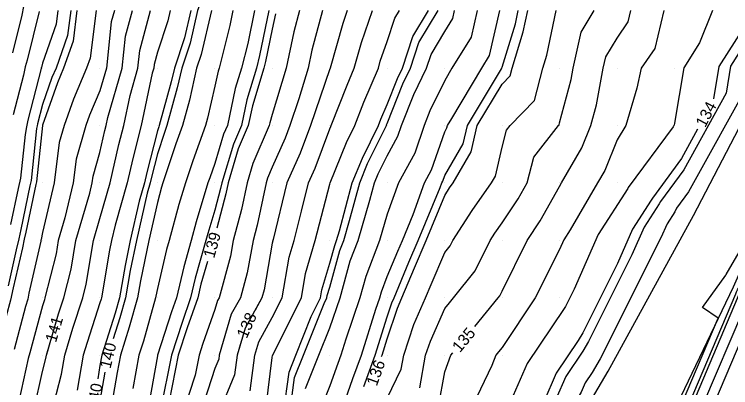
# Model space of a CAD drawing. Extents: x 2354170 to 2357230, y 866100 to 868290.
# Drawn here: x 2355375.1 to 2355499.8, y 866884.4 to 866949.4 of the extents above; entities that cross this region are included whole.
import ezdxf

# ---------------------------------------------------------------- set-up
doc = ezdxf.new("R2010")
doc.units = 0
for name, color, linetype in [('Default', 7, 'Continuous'), ('DTM Contours Major', 7, 'Continuous'), ('DTM Contours Major Text', 7, 'Continuous'), ('DTM Contours Minor', 7, 'Continuous'), ('DTM Contours Minor Text', 7, 'Continuous'), ('Exist DTM QL2 LIDAR Elevation Point', 7, 'Continuous'), ('PH Exist DTM Breakline', 7, 'Continuous')]:
    doc.layers.add(name, color=color, linetype=linetype)

msp = doc.modelspace()

# ---------------------------------------------------------------- linework, layer by layer
at = {"layer": 'Default'}
for points in [[(2355539.7, 867022.97), (2355537.35, 867020.38), (2355536.13, 867013.98), (2355531.41, 867003.55), (2355526.83, 866996.95), (2355526.72, 866996.73), (2355525.78, 866991.54), (2355519.66, 866978.94), (2355514.25, 866974.05), (2355510.02, 866968.44), (2355508.26, 866963), (2355506.26, 866955.52), (2355502.1, 866947.16), (2355497.72, 866940.29), (2355496.77, 866934.66)], [(2355490.12, 866875.79), (2355491.48, 866878.23), (2355491.88, 866879.06), (2355492.3, 866879.89), (2355492.7, 866880.74), (2355493.15, 866881.59), (2355500.95, 866899.94), (2355501.19, 866900.53), (2355501.44, 866901.06), (2355501.7, 866901.6), (2355501.96, 866902.13), (2355511.01, 866921.79), (2355511.33, 866922.42), (2355511.64, 866923.07), (2355511.95, 866923.71), (2355512.25, 866924.35), (2355512.56, 866924.99), (2355522.34, 866944.6), (2355522.74, 866945.44), (2355523.14, 866946.28), (2355523.54, 866947.12), (2355531.35, 866962.66)], [(2355374.81, 866942.66), (2355376.43, 866949.19), (2355376.71, 866950.72)], [(2355385.98, 866950.01), (2355385.32, 866944.67), (2355383.66, 866940.01), (2355382.56, 866937.42), (2355379.98, 866930.07), (2355379.96, 866930.02), (2355379.96, 866930.01), (2355379.96, 866930), (2355378.91, 866920.23), (2355378.8, 866919.75), (2355377.07, 866911.45), (2355376.81, 866910.21), (2355376.47, 866908.73), (2355374.89, 866901.78), (2355374.43, 866899.58), (2355373.67, 866896.84), (2355372.26, 866891.59), (2355371.91, 866890.32)], [(2355382.66, 866950.01), (2355382.36, 866947.62), (2355379.98, 866940.88), (2355379.78, 866940.11), (2355379.76, 866940.02), (2355379.74, 866939.92), (2355377.41, 866930.93), (2355377.19, 866929.78), (2355376.94, 866928.44), (2355376.12, 866920.82), (2355375.74, 866919.06), (2355374.42, 866912.77)], [(2355374.59, 866852.56), (2355376.35, 866859.24), (2355376.76, 866860.65), (2355379.04, 866869.55), (2355379.14, 866869.95), (2355379.23, 866870.27), (2355379.98, 866873.65), (2355381.33, 866878.66), (2355381.57, 866880.01), (2355383.28, 866886.7), (2355383.86, 866890.01), (2355385.26, 866894.73), (2355386.97, 866900.01), (2355387.58, 866902.41), (2355388.84, 866910.01), (2355389.98, 866913.85), (2355391.75, 866920.01), (2355393.27, 866926.71), (2355394.11, 866930.01), (2355395.21, 866935.24), (2355396.59, 866940.01), (2355396.91, 866943.08), (2355398.78, 866950.01)], [(2355379.41, 866949.88), (2355377.3, 866941.39), (2355376.95, 866940.21), (2355376.65, 866938.76), (2355374.86, 866931.85)], [(2355392.49, 866950.01), (2355391.95, 866948.03), (2355391.13, 866940.01), (2355389.98, 866936.05), (2355388.17, 866931.81), (2355387.54, 866930.01), (2355385.84, 866924.14), (2355385.33, 866920.01), (2355383.89, 866913.92), (2355382.73, 866910.01), (2355382.34, 866907.65), (2355380.4, 866900.01), (2355380.3, 866899.69), (2355379.98, 866898.61), (2355377.79, 866890.46), (2355377.51, 866889.47), (2355375.87, 866882), (2355375.45, 866880.29), (2355374.91, 866878.2)], [(2355389.31, 866950.01), (2355388.27, 866941.72), (2355387.66, 866940.01), (2355385.37, 866934.62), (2355383.75, 866930.01), (2355382.9, 866927.08), (2355382.02, 866920.01), (2355379.98, 866911.38), (2355379.72, 866910.14), (2355379.69, 866910.03), (2355379.66, 866909.9), (2355377.61, 866900.84), (2355377.4, 866899.81), (2355377.04, 866898.53), (2355375.02, 866891.02)], [(2355382.76, 866897.15), (2355382.78, 866897.21), (2355383.69, 866900.01), (2355384.96, 866905.03), (2355385.79, 866910.01), (2355388.22, 866918.26), (2355388.64, 866920.01), (2355388.79, 866921.2), (2355389.98, 866925.32), (2355390.84, 866929.14), (2355391.06, 866930.01), (2355391.35, 866931.39), (2355393.86, 866940.01), (2355394.43, 866945.55), (2355395.63, 866950.01)], [(2355402.2, 866950.01), (2355401.78, 866948.21), (2355399.98, 866942.78), (2355399.39, 866940.6), (2355399.33, 866940.01), (2355399.06, 866939.1), (2355397.16, 866930.01), (2355395.7, 866924.28), (2355394.73, 866920.01), (2355392.61, 866912.64), (2355392.01, 866910.01), (2355391.66, 866908.33), (2355390.24, 866900.01), (2355390.19, 866899.8), (2355389.98, 866899.14), (2355387.74, 866892.25), (2355387.07, 866890.01), (2355386.02, 866883.96)], [(2355405.79, 866950.01), (2355404.69, 866945.29), (2355402.94, 866940.01), (2355402.39, 866937.6), (2355400.29, 866930.01), (2355400.21, 866929.78), (2355399.98, 866929.08), (2355398.13, 866921.85), (2355397.72, 866920.01), (2355396.8, 866916.83), (2355395.24, 866910.01), (2355394.34, 866905.65), (2355393.38, 866900.01), (2355392.64, 866897.35), (2355390.29, 866890.01), (2355390.24, 866889.74), (2355389.98, 866888.22), (2355389.58, 866885.91)], [(2355409.37, 866950.01), (2355407.6, 866942.38), (2355406.81, 866940.01), (2355405.55, 866934.43), (2355404.33, 866930.01), (2355403.16, 866926.82), (2355400.93, 866920.01), (2355400.71, 866919.28), (2355399.98, 866916.59), (2355398.47, 866910.01), (2355397.02, 866902.97), (2355396.51, 866900.01), (2355395.09, 866894.9), (2355393.53, 866890.01), (2355392.98, 866887), (2355391.76, 866880.01)], [(2355413.11, 866950.01), (2355412.57, 866947.41), (2355410.7, 866940.01), (2355410.53, 866939.45), (2355409.98, 866936.84), (2355408.71, 866931.27), (2355408.36, 866930.01), (2355406.12, 866923.87), (2355404.85, 866920.01), (2355403.73, 866916.26), (2355402.03, 866910.01), (2355401.57, 866908.41), (2355399.98, 866901.65), (2355399.69, 866900.29), (2355399.65, 866900.01), (2355397.54, 866892.45), (2355396.76, 866890.01), (2355395.72, 866884.26)], [(2355416.88, 866950.01), (2355415.69, 866944.29), (2355414.61, 866940.01), (2355413.53, 866936.45), (2355412.16, 866930.01), (2355411.51, 866928.48), (2355409.98, 866923.37), (2355409.08, 866920.91), (2355408.78, 866920.01), (2355406.75, 866913.24), (2355405.87, 866910.01), (2355404.57, 866905.42), (2355403.29, 866900.01), (2355402.43, 866897.56), (2355400, 866890.01), (2355399.98, 866889.9), (2355398.46, 866881.52)], [(2355424.72, 866950.01), (2355423.7, 866946.29), (2355422.38, 866940.01), (2355419.98, 866931.92), (2355419.53, 866930.45), (2355419.44, 866930.01), (2355416.61, 866923.37), (2355415.6, 866920.01), (2355414.6, 866915.39), (2355413.18, 866910.01), (2355412.7, 866907.28), (2355410.7, 866900.01), (2355410.44, 866899.55), (2355409.98, 866897.97), (2355407.91, 866892.08), (2355407.24, 866890.01), (2355406.55, 866886.58), (2355404.41, 866880.01)], [(2355433.03, 866950.01), (2355432.24, 866947.74), (2355430.04, 866940.01), (2355430.02, 866939.96), (2355429.98, 866939.85), (2355426.62, 866930.01), (2355424.8, 866925.18), (2355422.53, 866920.01), (2355420.1, 866910.14), (2355420.07, 866910.01), (2355420.05, 866909.94), (2355419.98, 866909.51), (2355418.55, 866901.43), (2355418.16, 866900.01), (2355415.23, 866894.76), (2355413.84, 866890.01), (2355413.39, 866886.59), (2355410.67, 866880.01), (2355410.5, 866879.49), (2355409.98, 866877.99), (2355408.27, 866871.72), (2355407.71, 866870.01), (2355406.7, 866866.73), (2355405.8, 866863.82)], [(2355428.74, 866950.01), (2355426.86, 866943.12), (2355426.21, 866940.01), (2355424.62, 866934.65), (2355423.03, 866930.01), (2355422.2, 866927.79), (2355419.98, 866922.74), (2355419.16, 866920.82), (2355418.92, 866920.01), (2355417.32, 866912.66), (2355416.62, 866910.01), (2355415.63, 866904.36), (2355414.43, 866900.01), (2355412.83, 866897.15), (2355410.74, 866890.01), (2355410.65, 866889.33), (2355409.98, 866887.7), (2355407.47, 866880.01)], [(2355420.54, 866949.45), (2355419.98, 866946.78), (2355418.82, 866941.17), (2355418.52, 866940.01), (2355416.53, 866933.45), (2355415.8, 866930.01), (2355414.06, 866925.93), (2355412.28, 866920.01), (2355411.87, 866918.11), (2355410.3, 866912.12)], [(2355416.14, 866883.85), (2355416.93, 866890.01), (2355417.62, 866892.36), (2355419.98, 866896.58), (2355421.69, 866900.01), (2355422.9, 866907.09), (2355423.76, 866910.01), (2355425.08, 866915.11), (2355426.28, 866920.01), (2355427.41, 866922.58), (2355429.98, 866929.41), (2355430.15, 866929.84), (2355430.23, 866930.01), (2355432.98, 866937.01), (2355434.24, 866940.01), (2355435.51, 866944.48), (2355437.44, 866950.01)], [(2355418.88, 866881.1), (2355419.98, 866889.6), (2355420.03, 866889.96), (2355420.04, 866890.01), (2355420.09, 866890.12), (2355425.03, 866900.01), (2355425.75, 866904.23), (2355427.46, 866910.01), (2355429.98, 866919.81), (2355430.03, 866920.01), (2355432.9, 866927.08), (2355434.35, 866930.01), (2355435.93, 866934.05), (2355438.44, 866940.01), (2355438.78, 866941.21), (2355439.98, 866944.65), (2355441.31, 866948.68), (2355442.11, 866950.01)], [(2355420.88, 866876.24), (2355421.93, 866880.01), (2355422.89, 866887.09), (2355424.06, 866890.01), (2355426.76, 866896.79), (2355428.37, 866900.01), (2355428.6, 866901.38), (2355429.98, 866906.04), (2355430.84, 866909.15), (2355431.16, 866910.01), (2355431.66, 866911.69), (2355433.9, 866920.01), (2355435.66, 866924.33), (2355438.47, 866930.01), (2355438.89, 866931.09), (2355439.98, 866933.68), (2355441.77, 866938.22), (2355442.63, 866940.01), (2355444.46, 866945.53), (2355447.14, 866950.01)], [(2355425.76, 866884.23), (2355428.08, 866890.01), (2355429.98, 866894.77), (2355431.77, 866900.01), (2355433.54, 866906.44), (2355434.9, 866910.01), (2355436.96, 866917), (2355437.77, 866920.01), (2355438.41, 866921.58), (2355439.98, 866924.74), (2355441.83, 866928.16), (2355442.47, 866930.01), (2355444.59, 866935.39), (2355446.82, 866940.01), (2355447.6, 866942.38), (2355449.98, 866946.35), (2355451.38, 866948.61), (2355451.69, 866950.01)], [(2355455.63, 866950.01), (2355454.59, 866945.4), (2355451.25, 866940.01), (2355449.98, 866937.87), (2355447.42, 866932.57), (2355446.41, 866930.01), (2355444.76, 866925.22), (2355441.93, 866920.01), (2355439.98, 866914.55), (2355438.64, 866910.01), (2355436.25, 866903.73), (2355435.22, 866900.01), (2355432.75, 866892.79), (2355431.88, 866890.01), (2355431.37, 866888.61), (2355429.98, 866884.72), (2355428.63, 866881.36)], [(2355431.88, 866880.01), (2355434.01, 866885.97), (2355435.48, 866890.01), (2355438, 866898.04), (2355438.68, 866900.01), (2355438.96, 866901.03), (2355439.98, 866903.7), (2355441.84, 866908.15), (2355442.62, 866910.01), (2355444.49, 866914.52), (2355446.45, 866920.01), (2355447.69, 866922.29), (2355449.98, 866928.93), (2355450.38, 866929.61), (2355450.47, 866930.01), (2355451.2, 866931.24), (2355456.46, 866940.01), (2355457.8, 866942.18), (2355459.57, 866950.01)], [(2355439, 866889.81), (2355439.08, 866890.01), (2355439.98, 866892.87), (2355441.77, 866898.22), (2355442.55, 866900.01), (2355444.74, 866905.25), (2355446.75, 866910.01), (2355449.98, 866917.81), (2355450.84, 866919.14), (2355451.45, 866920.01), (2355454.59, 866925.4), (2355455.66, 866930.01), (2355459.98, 866937.21), (2355461.36, 866938.63), (2355461.71, 866940.01), (2355463.66, 866946.33), (2355464.43, 866950.01)], [(2355439.98, 866882.57), (2355442.4, 866887.58), (2355442.85, 866890.01), (2355444.63, 866895.35), (2355446.67, 866900.01), (2355447.64, 866902.34), (2355449.98, 866907.88), (2355450.92, 866909.06), (2355451.4, 866910.01), (2355454.79, 866915.2), (2355458.12, 866920.01), (2355458.8, 866921.18), (2355459.98, 866926.26), (2355460.77, 866929.22), (2355461.38, 866930.01), (2355465.62, 866934.37), (2355467.08, 866940.01), (2355467.76, 866942.23), (2355469.4, 866950.01)], [(2355445.64, 866884.34), (2355446.67, 866890.01), (2355447.5, 866892.48), (2355449.98, 866898.16), (2355450.81, 866899.17), (2355451.5, 866900.01), (2355455.26, 866904.73), (2355457.91, 866910.01), (2355458.73, 866911.26), (2355459.98, 866913.06), (2355462.75, 866917.23), (2355464.31, 866920.01), (2355465.51, 866924.48), (2355469.79, 866930.01), (2355469.88, 866930.11), (2355469.98, 866930.48), (2355472, 866937.99), (2355472.37, 866940.01), (2355473.74, 866946.24), (2355476.02, 866950.01)], [(2355488.12, 866950.01), (2355486.57, 866943.41), (2355484.21, 866940.01), (2355483.45, 866936.53), (2355481.5, 866930.01), (2355479.98, 866927.49), (2355477.83, 866922.15), (2355476.6, 866920.01), (2355471.83, 866911.86), (2355470.71, 866910.12), (2355469.98, 866908.45), (2355465.76, 866900.01), (2355459.98, 866891.37), (2355459.36, 866890.62), (2355458.86, 866890.01), (2355458.2, 866888.23), (2355454.24, 866880.01)], [(2355455.21, 866895.04), (2355459.29, 866900.01), (2355459.59, 866900.39), (2355459.98, 866901.16), (2355464.35, 866910.01), (2355466.6, 866913.39), (2355469.98, 866919.4), (2355470.34, 866920.01), (2355473.86, 866926.13), (2355475.42, 866930.01), (2355476.39, 866933.6), (2355477.58, 866940.01), (2355478.01, 866941.98), (2355479.98, 866945.23), (2355481.94, 866948.05), (2355482.4, 866950.01)], [(2355496.62, 866950.01), (2355494.36, 866944.4), (2355491.61, 866940.07), (2355489.98, 866930.39), (2355489.91, 866930.08), (2355489.89, 866930.01), (2355489.75, 866929.78), (2355481.91, 866919.19), (2355481.86, 866919.07), (2355476.71, 866911.06), (2355472.51, 866901.51), (2355470.99, 866898.49), (2355470.79, 866898.14), (2355464.31, 866888.57), (2355460.7, 866880.2)], [(2355503.48, 866938.45), (2355492.43, 866918.44), (2355490.34, 866915.6), (2355490.03, 866914.99), (2355488.7, 866912.92), (2355487.62, 866910.45), (2355477.05, 866889.38), (2355475.65, 866887.01), (2355474.42, 866885.19), (2355473.74, 866883.61), (2355461.28, 866862.43), (2355460.02, 866860.08), (2355459.53, 866858.81), (2355448.95, 866839.68), (2355447.87, 866837.23), (2355447.14, 866836.16), (2355446.82, 866835.2), (2355446.46, 866833.87), (2355439.61, 866809.83), (2355439.23, 866808.12), (2355439.11, 866807.83), (2355438.55, 866806.26), (2355437.92, 866804.37), (2355429.32, 866784.47)], [(2355494.01, 866929.35), (2355491.2, 866924.25), (2355486.13, 866917.39), (2355485.94, 866917.03), (2355482.7, 866911.99), (2355480.06, 866905.98), (2355474.02, 866893.93), (2355473.22, 866892.57), (2355469.36, 866886.88), (2355467.22, 866881.91), (2355460.66, 866870.76), (2355456.71, 866863.35), (2355455.18, 866859.36), (2355449.42, 866848.95), (2355446.26, 866841.78)], [(2355491.22, 866881.44), (2355497.59, 866896.45), (2355494.87, 866898.31), (2355498.89, 866903.97), (2355498.97, 866904.09), (2355508.04, 866919.61)], [(2355408.67, 866906.34), (2355407.56, 866902.42), (2355406.99, 866900.01), (2355405.17, 866894.82), (2355403.62, 866890.01), (2355402.01, 866882.04)], [(2355495.09, 866881.73), (2355501.85, 866897.64)], [(2355497.02, 866881.87), (2355502.75, 866895.35)], [(2355373.83, 866861.24), (2355375.52, 866867.82), (2355375.99, 866869.7), (2355376.4, 866871.23), (2355378.21, 866879.38), (2355378.4, 866880.11), (2355378.54, 866880.71), (2355379.98, 866887.21), (2355380.55, 866889.44), (2355380.65, 866890.01), (2355381.06, 866891.39)], [(2355418.99, 866796.76), (2355419.98, 866799.57), (2355420.14, 866800.06), (2355420.2, 866800.23), (2355421.52, 866810.01), (2355422.2, 866812.23), (2355425.56, 866820.01), (2355427.79, 866827.82), (2355428.53, 866830.01), (2355429.98, 866834.51), (2355431.65, 866839.63), (2355436.23, 866846.26), (2355438.38, 866850.01), (2355439.98, 866856.34), (2355440.75, 866860.01), (2355442.56, 866867.43), (2355443.91, 866870.01), (2355446.47, 866876.5), (2355448.35, 866880.01), (2355448.88, 866881.11), (2355449.98, 866887.14), (2355451.04, 866890.01), (2355451.38, 866890.42)]]:
    msp.add_lwpolyline(points, dxfattribs=at)
at = {"layer": 'DTM Contours Major'}
for points in [[(2355416.98, 866989.64), (2355415.21, 866984.78), (2355414.25, 866980.01), (2355413.42, 866976.56), (2355412.36, 866970.01), (2355412, 866967.98), (2355409.98, 866960.18), (2355409.93, 866960.01), (2355407.75, 866952.23), (2355406.98, 866950.01), (2355405.66, 866944.32), (2355404.23, 866940.01), (2355403.44, 866936.54), (2355401.64, 866930.01), (2355401.19, 866928.79), (2355399.98, 866925.09), (2355398.94, 866921.04), (2355398.71, 866920.01), (2355398.2, 866918.23), (2355396.31, 866910.01), (2355395.23, 866904.76), (2355394.42, 866900.01), (2355393.45, 866896.53), (2355392.29, 866892.88)], [(2355455.21, 866895.04), (2355459.29, 866900.01), (2355459.59, 866900.39), (2355459.98, 866901.16), (2355464.35, 866910.01), (2355466.6, 866913.39), (2355469.98, 866919.4), (2355470.34, 866920.01), (2355473.86, 866926.13), (2355475.42, 866930.01), (2355476.39, 866933.6), (2355477.58, 866940.01), (2355478.01, 866941.98), (2355479.98, 866945.23), (2355481.94, 866948.05), (2355482.4, 866950.01)], [(2355418.99, 866796.76), (2355419.98, 866799.57), (2355420.14, 866800.06), (2355420.2, 866800.23), (2355421.52, 866810.01), (2355422.2, 866812.23), (2355425.56, 866820.01), (2355427.79, 866827.82), (2355428.53, 866830.01), (2355429.98, 866834.51), (2355431.65, 866839.63), (2355436.23, 866846.26), (2355438.38, 866850.01), (2355439.98, 866856.34), (2355440.75, 866860.01), (2355442.56, 866867.43), (2355443.91, 866870.01), (2355446.47, 866876.5), (2355448.35, 866880.01), (2355448.88, 866881.11), (2355449.98, 866887.14), (2355451.04, 866890.01), (2355451.38, 866890.42)], [(2355390.85, 866887.07), (2355389.98, 866882.06), (2355389.67, 866880.31), (2355389.59, 866880.01), (2355388.14, 866871.84), (2355387.64, 866870.01), (2355385.8, 866864.19), (2355384.52, 866860.01), (2355383.14, 866856.85), (2355381.26, 866850.01), (2355381, 866848.98), (2355379.98, 866842.55), (2355379.57, 866840.14), (2355379.51, 866839.97), (2355379.46, 866839.77), (2355377.07, 866830.57), (2355376.75, 866829.35), (2355374.65, 866822.42)]]:
    msp.add_lwpolyline(points, dxfattribs=at)
at = {"layer": 'DTM Contours Minor'}
for points in [[(2355486.24, 866870.01), (2355491.23, 866878.97), (2355491.54, 866879.61), (2355491.86, 866880.24), (2355492.17, 866880.89), (2355492.51, 866881.54), (2355500.65, 866900.71), (2355500.8, 866901.06), (2355500.95, 866901.39), (2355501.11, 866901.71), (2355501.27, 866902.04), (2355510.7, 866922.55), (2355510.92, 866922.97), (2355511.13, 866923.41), (2355511.34, 866923.85), (2355511.55, 866924.29), (2355511.76, 866924.72), (2355521.96, 866945.17), (2355522.26, 866945.82), (2355522.57, 866946.46), (2355522.88, 866947.1), (2355531.03, 866963.31)], [(2355509.43, 866958.31), (2355503.17, 866945.72), (2355499.76, 866940.36), (2355498.96, 866935.62), (2355491.61, 866922.31), (2355487.53, 866916.8), (2355487.31, 866916.35), (2355484.7, 866912.3), (2355482.58, 866907.47), (2355475.03, 866892.42), (2355474.03, 866890.72), (2355471.05, 866886.32), (2355469.39, 866882.47), (2355460.87, 866867.99), (2355457.81, 866862.26), (2355456.63, 866859.17), (2355453.78, 866854.03)], [(2355373.83, 866861.24), (2355375.52, 866867.82), (2355375.99, 866869.7), (2355376.4, 866871.23), (2355378.21, 866879.38), (2355378.4, 866880.11), (2355378.54, 866880.71), (2355379.98, 866887.21), (2355380.55, 866889.44), (2355380.65, 866890.01), (2355382.78, 866897.21), (2355383.69, 866900.01), (2355384.96, 866905.03), (2355385.79, 866910.01), (2355388.22, 866918.26), (2355388.64, 866920.01), (2355388.79, 866921.2), (2355389.98, 866925.32), (2355390.84, 866929.14), (2355391.06, 866930.01), (2355391.35, 866931.39), (2355393.86, 866940.01), (2355394.43, 866945.55), (2355395.63, 866950.01)], [(2355384.88, 866950.01), (2355384.33, 866945.65), (2355382.33, 866940.01), (2355381.63, 866938.36), (2355379.98, 866933.66), (2355379.11, 866930.32), (2355379.04, 866929.93), (2355378.95, 866929.48), (2355377.98, 866920.43), (2355377.78, 866919.52), (2355376.19, 866911.89), (2355375.85, 866910.27), (2355375.4, 866908.35), (2355373.99, 866902.1)], [(2355419.39, 866950.01), (2355417.77, 866942.21), (2355417.22, 866940.01), (2355415.53, 866934.45), (2355414.59, 866930.01), (2355413.21, 866926.78), (2355411.18, 866920.01), (2355410.96, 866919.02), (2355409.98, 866915.27), (2355408.76, 866911.22), (2355408.43, 866910.01), (2355406.56, 866903.42), (2355405.76, 866900.01), (2355404.26, 866895.73), (2355402.41, 866890.01), (2355400.49, 866880.53)], [(2355433.03, 866950.01), (2355432.24, 866947.74), (2355430.04, 866940.01), (2355430.02, 866939.96), (2355429.98, 866939.85), (2355426.62, 866930.01), (2355424.8, 866925.18), (2355422.53, 866920.01), (2355420.1, 866910.14), (2355420.07, 866910.01), (2355420.05, 866909.94), (2355419.98, 866909.51), (2355418.55, 866901.43), (2355418.16, 866900.01), (2355416.97, 866897.88)], [(2355423.02, 866880.01), (2355423.85, 866886.14), (2355425.4, 866890.01), (2355428.98, 866899.02), (2355429.48, 866900.01), (2355429.55, 866900.43), (2355429.98, 866901.87), (2355431.74, 866908.25), (2355432.41, 866910.01), (2355433.43, 866913.46), (2355435.19, 866920.01), (2355436.57, 866923.41), (2355439.84, 866930.01), (2355439.88, 866930.11), (2355439.98, 866930.35), (2355442.71, 866937.28), (2355444.02, 866940.01), (2355445.5, 866944.48), (2355448.82, 866950.01)], [(2355435.91, 866884.59), (2355437.88, 866890.01), (2355439.98, 866896.68), (2355440.81, 866899.17), (2355441.18, 866900.01), (2355443.77, 866906.21), (2355445.37, 866910.01), (2355449.18, 866919.21), (2355449.46, 866920.01), (2355449.64, 866920.34), (2355449.98, 866921.3), (2355453.18, 866926.8), (2355453.93, 866930.01), (2355459.85, 866939.88), (2355459.93, 866940.01), (2355459.94, 866940.04), (2355459.98, 866940.18), (2355462.29, 866947.7), (2355462.78, 866950.01)], [(2355414.55, 866892.43), (2355413.84, 866890.01), (2355413.39, 866886.59), (2355410.67, 866880.01)]]:
    msp.add_lwpolyline(points, dxfattribs=at)
at = {"layer": 'Exist DTM QL2 LIDAR Elevation Point'}
for p, q in [((2355379.98, 866940.01), (2355379.98, 866940.01)), ((2355389.98, 866940.01), (2355389.98, 866940.01)), ((2355399.98, 866940.01), (2355399.98, 866940.01)), ((2355409.98, 866940.01), (2355409.98, 866940.01)), ((2355419.98, 866940.01), (2355419.98, 866940.01)), ((2355429.98, 866940.01), (2355429.98, 866940.01)), ((2355439.98, 866940.01), (2355439.98, 866940.01)), ((2355449.98, 866940.01), (2355449.98, 866940.01)), ((2355459.98, 866940.01), (2355459.98, 866940.01)), ((2355469.98, 866940.01), (2355469.98, 866940.01)), ((2355479.98, 866940.01), (2355479.98, 866940.01)), ((2355489.98, 866940.01), (2355489.98, 866940.01)), ((2355379.98, 866930.01), (2355379.98, 866930.01)), ((2355389.98, 866930.01), (2355389.98, 866930.01)), ((2355399.98, 866930.01), (2355399.98, 866930.01)), ((2355409.98, 866930.01), (2355409.98, 866930.01)), ((2355419.98, 866930.01), (2355419.98, 866930.01)), ((2355429.98, 866930.01), (2355429.98, 866930.01)), ((2355439.98, 866930.01), (2355439.98, 866930.01)), ((2355449.98, 866930.01), (2355449.98, 866930.01)), ((2355459.98, 866930.01), (2355459.98, 866930.01)), ((2355469.98, 866930.01), (2355469.98, 866930.01)), ((2355479.98, 866930.01), (2355479.98, 866930.01)), ((2355489.98, 866930.01), (2355489.98, 866930.01)), ((2355379.98, 866920.01), (2355379.98, 866920.01)), ((2355389.98, 866920.01), (2355389.98, 866920.01)), ((2355399.98, 866920.01), (2355399.98, 866920.01)), ((2355409.98, 866920.01), (2355409.98, 866920.01)), ((2355419.98, 866920.01), (2355419.98, 866920.01)), ((2355429.98, 866920.01), (2355429.98, 866920.01)), ((2355439.98, 866920.01), (2355439.98, 866920.01)), ((2355449.98, 866920.01), (2355449.98, 866920.01)), ((2355459.98, 866920.01), (2355459.98, 866920.01)), ((2355469.98, 866920.01), (2355469.98, 866920.01)), ((2355479.98, 866920.01), (2355479.98, 866920.01)), ((2355379.98, 866910.01), (2355379.98, 866910.01)), ((2355389.98, 866910.01), (2355389.98, 866910.01)), ((2355399.98, 866910.01), (2355399.98, 866910.01)), ((2355409.98, 866910.01), (2355409.98, 866910.01)), ((2355419.98, 866910.01), (2355419.98, 866910.01)), ((2355429.98, 866910.01), (2355429.98, 866910.01)), ((2355439.98, 866910.01), (2355439.98, 866910.01)), ((2355449.98, 866910.01), (2355449.98, 866910.01)), ((2355459.98, 866910.01), (2355459.98, 866910.01)), ((2355469.98, 866910.01), (2355469.98, 866910.01)), ((2355379.98, 866900.01), (2355379.98, 866900.01)), ((2355389.98, 866900.01), (2355389.98, 866900.01)), ((2355399.98, 866900.01), (2355399.98, 866900.01)), ((2355409.98, 866900.01), (2355409.98, 866900.01)), ((2355419.98, 866900.01), (2355419.98, 866900.01)), ((2355429.98, 866900.01), (2355429.98, 866900.01)), ((2355439.98, 866900.01), (2355439.98, 866900.01)), ((2355449.98, 866900.01), (2355449.98, 866900.01)), ((2355459.98, 866900.01), (2355459.98, 866900.01)), ((2355469.98, 866900.01), (2355469.98, 866900.01)), ((2355379.98, 866890.01), (2355379.98, 866890.01)), ((2355389.98, 866890.01), (2355389.98, 866890.01)), ((2355399.98, 866890.01), (2355399.98, 866890.01)), ((2355409.98, 866890.01), (2355409.98, 866890.01)), ((2355419.98, 866890.01), (2355419.98, 866890.01)), ((2355429.98, 866890.01), (2355429.98, 866890.01)), ((2355439.98, 866890.01), (2355439.98, 866890.01)), ((2355449.98, 866890.01), (2355449.98, 866890.01)), ((2355459.98, 866890.01), (2355459.98, 866890.01))]:
    msp.add_line(p, q, dxfattribs=at)
at = {"layer": 'PH Exist DTM Breakline'}
for points in [[(2355623.28, 867155.35), (2355615.58, 867138.25), (2355608.49, 867123.33), (2355597.58, 867101.03), (2355584.19, 867076.32), (2355571.68, 867051.84), (2355556.97, 867022.36), (2355542.39, 866991.35), (2355529.82, 866965.71), (2355520.72, 866947.04), (2355510.06, 866924.14), (2355500.19, 866901.89), (2355490.41, 866881.38), (2355478.72, 866859.36), (2355464.61, 866830.77), (2355451.41, 866802.43), (2355436.87, 866776.84), (2355421.46, 866750.82), (2355406.88, 866726.28), (2355400.07, 866711.56)], [(2355400.07, 866711.56), (2355405.9, 866730.25), (2355416.39, 866751.72), (2355427.36, 866780.81), (2355441.71, 866807.61), (2355448.76, 866835.8), (2355461.56, 866858.55), (2355478.46, 866887.26), (2355493.3, 866914.34), (2355506.97, 866940.62), (2355519.32, 866966.99), (2355533.54, 866993.95), (2355547.1, 867021.46), (2355560.37, 867044.81), (2355572.32, 867070.57), (2355587.94, 867097.01), (2355600.74, 867121.89), (2355610.75, 867143.33), (2355613.41, 867148.1), (2355613.42, 867152.41)]]:
    msp.add_lwpolyline(points, dxfattribs=at)

# ---------------------------------------------------------------- texts
at = {"layer": 'Default'}
for s, rotation, p in [('134', 62.5455, (2355495.32, 866929.53)), ('139', 74.3135, (2355409.85, 866906.8)), ('141', 73.5194, (2355382.32, 866892.13)), ('135', 50.392, (2355452.63, 866890.36)), ('136', 70.0723, (2355438.16, 866884.54)), ('140', 79.1994, (2355389.62, 866880.54))]:
    msp.add_text(s, height=2, rotation=rotation, dxfattribs=at).set_placement(p)
at = {"layer": 'DTM Contours Major Text'}
for s, rotation, p in [('135', 50.392, (2355452.63, 866890.36)), ('140', 76.1008, (2355391.8, 866887.57))]:
    msp.add_text(s, height=2, rotation=rotation, dxfattribs=at).set_placement(p)
at = {"layer": 'DTM Contours Minor Text'}
msp.add_text('138', height=2, rotation=66.0055, dxfattribs=at).set_placement((2355415.51, 866892.8))

doc.saveas('drawing.dxf')
